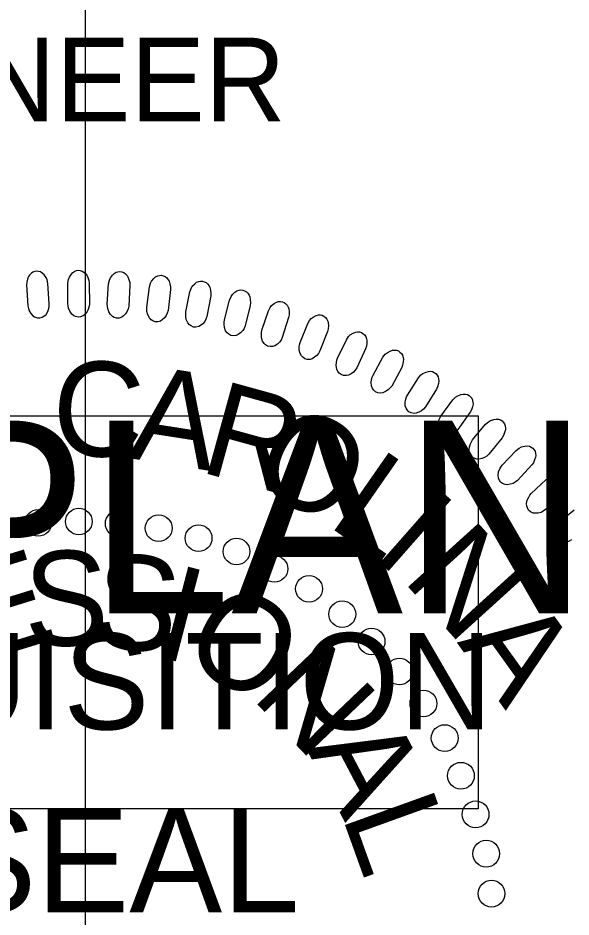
# Model space of a CAD drawing. Extents: x 505602 to 507286, y 483109 to 484209.
# Drawn here: x 507215 to 507248.1, y 484096 to 484149.8 of the extents above; entities that cross this region are included whole.
import ezdxf

# ---------------------------------------------------------------- set-up
doc = ezdxf.new("R2010")
doc.units = 0
for name, color, linetype in [('Sheet Layout Profile Border Port 2', 7, 'Continuous'), ('Sheet PE Seal Cell', 7, 'Continuous'), ('Sheet Profile CELL', 7, 'Continuous'), ('Sheet Sticker Incomplete CELL', 7, 'Continuous')]:
    doc.layers.add(name, color=color, linetype=linetype)

msp = doc.modelspace()

# ---------------------------------------------------------------- linework, layer by layer
at = {"layer": 'Sheet Layout Profile Border Port 2'}
msp.add_lwpolyline([(506919.08, 484183.712), (507219.08, 484183.712), (507219.08, 483683.712), (506919.08, 483683.712)], close=True, dxfattribs=at)
at = {"layer": 'Sheet PE Seal Cell'}
for points in [[(507218.035, 484132.707), (507218.035, 484133.933), (507218.073, 484134.153), (507218.126, 484134.293), (507218.238, 484134.462), (507218.335, 484134.572), (507218.447, 484134.651), (507218.551, 484134.691), (507218.664, 484134.711), (507218.776, 484134.691), (507218.896, 484134.661), (507219, 484134.601), (507219.105, 484134.502), (507219.165, 484134.421), (507219.232, 484134.272), (507219.292, 484134.092), (507219.314, 484133.933), (507219.321, 484132.677), (507219.299, 484132.507), (507219.253, 484132.367), (507219.164, 484132.208), (507219.052, 484132.068), (507218.954, 484131.988), (507218.797, 484131.929), (507218.648, 484131.909), (507218.499, 484131.948), (507218.394, 484131.998), (507218.266, 484132.098), (507218.147, 484132.268), (507218.08, 484132.447), (507218.05, 484132.577)], [(507216.92, 484132.698), (507216.843, 484133.922), (507216.792, 484134.139), (507216.731, 484134.274), (507216.609, 484134.437), (507216.505, 484134.54), (507216.388, 484134.613), (507216.281, 484134.646), (507216.168, 484134.659), (507216.057, 484134.632), (507215.94, 484134.595), (507215.839, 484134.529), (507215.741, 484134.422), (507215.687, 484134.339), (507215.628, 484134.186), (507215.58, 484134.003), (507215.568, 484133.842), (507215.639, 484132.587), (507215.671, 484132.42), (507215.725, 484132.283), (507215.824, 484132.129), (507215.945, 484131.997), (507216.047, 484131.924), (507216.208, 484131.873), (507216.358, 484131.863), (507216.505, 484131.912), (507216.606, 484131.969), (507216.727, 484132.076), (507216.835, 484132.253), (507216.891, 484132.436), (507216.913, 484132.568)], [(507220.394, 484132.68), (507220.472, 484133.905), (507220.522, 484134.121), (507220.584, 484134.257), (507220.707, 484134.419), (507220.81, 484134.523), (507220.927, 484134.595), (507221.034, 484134.628), (507221.148, 484134.641), (507221.258, 484134.614), (507221.376, 484134.577), (507221.476, 484134.51), (507221.575, 484134.404), (507221.629, 484134.321), (507221.687, 484134.167), (507221.735, 484133.984), (507221.748, 484133.824), (507221.675, 484132.569), (507221.643, 484132.401), (507221.589, 484132.265), (507221.489, 484132.112), (507221.369, 484131.979), (507221.267, 484131.905), (507221.106, 484131.856), (507220.955, 484131.845), (507220.809, 484131.894), (507220.708, 484131.951), (507220.587, 484132.059), (507220.479, 484132.235), (507220.423, 484132.418), (507220.401, 484132.55)], [(507222.757, 484132.505), (507222.911, 484133.722), (507222.975, 484133.935), (507223.045, 484134.067), (507223.177, 484134.221), (507223.288, 484134.318), (507223.409, 484134.382), (507223.518, 484134.409), (507223.631, 484134.415), (507223.74, 484134.381), (507223.855, 484134.336), (507223.951, 484134.264), (507224.043, 484134.151), (507224.092, 484134.065), (507224.141, 484133.908), (507224.176, 484133.722), (507224.179, 484133.561), (507224.028, 484132.314), (507223.985, 484132.148), (507223.923, 484132.016), (507223.814, 484131.868), (507223.685, 484131.744), (507223.579, 484131.677), (507223.415, 484131.637), (507223.265, 484131.636), (507223.121, 484131.695), (507223.024, 484131.757), (507222.91, 484131.872), (507222.812, 484132.056), (507222.769, 484132.242), (507222.755, 484132.375)], [(507225.096, 484132.219), (507225.326, 484133.423), (507225.404, 484133.632), (507225.482, 484133.759), (507225.624, 484133.904), (507225.74, 484133.994), (507225.865, 484134.051), (507225.975, 484134.071), (507226.089, 484134.07), (507226.195, 484134.029), (507226.307, 484133.977), (507226.399, 484133.898), (507226.483, 484133.781), (507226.527, 484133.692), (507226.565, 484133.532), (507226.59, 484133.344), (507226.582, 484133.183), (507226.354, 484131.947), (507226.299, 484131.786), (507226.229, 484131.657), (507226.111, 484131.517), (507225.975, 484131.401), (507225.864, 484131.341), (507225.699, 484131.311), (507225.548, 484131.32), (507225.409, 484131.387), (507225.316, 484131.456), (507225.21, 484131.577), (507225.124, 484131.766), (507225.091, 484131.955), (507225.087, 484132.088)], [(507227.402, 484131.745), (507227.707, 484132.933), (507227.797, 484133.136), (507227.883, 484133.258), (507228.034, 484133.395), (507228.155, 484133.477), (507228.284, 484133.526), (507228.395, 484133.538), (507228.509, 484133.53), (507228.612, 484133.483), (507228.721, 484133.424), (507228.807, 484133.34), (507228.883, 484133.218), (507228.922, 484133.125), (507228.949, 484132.963), (507228.963, 484132.775), (507228.945, 484132.614), (507228.639, 484131.395), (507228.575, 484131.237), (507228.496, 484131.113), (507228.37, 484130.981), (507228.227, 484130.874), (507228.113, 484130.82), (507227.946, 484130.802), (507227.796, 484130.82), (507227.662, 484130.896), (507227.573, 484130.97), (507227.474, 484131.098), (507227.4, 484131.292), (507227.38, 484131.483), (507227.383, 484131.615)], [(507229.651, 484131.123), (507230.031, 484132.289), (507230.134, 484132.487), (507230.227, 484132.603), (507230.386, 484132.73), (507230.513, 484132.804), (507230.644, 484132.845), (507230.756, 484132.85), (507230.869, 484132.835), (507230.969, 484132.781), (507231.073, 484132.715), (507231.155, 484132.626), (507231.223, 484132.499), (507231.255, 484132.405), (507231.273, 484132.242), (507231.274, 484132.053), (507231.247, 484131.894), (507230.865, 484130.697), (507230.791, 484130.542), (507230.705, 484130.423), (507230.571, 484130.299), (507230.42, 484130.201), (507230.304, 484130.155), (507230.136, 484130.147), (507229.987, 484130.175), (507229.858, 484130.259), (507229.774, 484130.338), (507229.684, 484130.472), (507229.622, 484130.67), (507229.614, 484130.862), (507229.626, 484130.995)], [(507231.935, 484130.388), (507232.387, 484131.528), (507232.502, 484131.718), (507232.602, 484131.829), (507232.769, 484131.945), (507232.9, 484132.012), (507233.034, 484132.044), (507233.145, 484132.043), (507233.257, 484132.02), (507233.353, 484131.96), (507233.454, 484131.888), (507233.529, 484131.794), (507233.59, 484131.663), (507233.616, 484131.567), (507233.624, 484131.403), (507233.613, 484131.214), (507233.575, 484131.057), (507233.119, 484129.886), (507233.035, 484129.737), (507232.942, 484129.624), (507232.8, 484129.509), (507232.645, 484129.42), (507232.525, 484129.381), (507232.357, 484129.384), (507232.211, 484129.421), (507232.086, 484129.513), (507232.007, 484129.597), (507231.926, 484129.737), (507231.878, 484129.939), (507231.881, 484130.13), (507231.901, 484130.262)], [(507234.176, 484129.454), (507234.699, 484130.563), (507234.826, 484130.746), (507234.933, 484130.85), (507235.107, 484130.956), (507235.241, 484131.014), (507235.376, 484131.038), (507235.488, 484131.029), (507235.598, 484131), (507235.691, 484130.934), (507235.787, 484130.856), (507235.856, 484130.757), (507235.908, 484130.622), (507235.928, 484130.525), (507235.925, 484130.36), (507235.903, 484130.173), (507235.855, 484130.019), (507235.326, 484128.879), (507235.234, 484128.735), (507235.134, 484128.628), (507234.984, 484128.521), (507234.824, 484128.443), (507234.701, 484128.412), (507234.534, 484128.425), (507234.39, 484128.471), (507234.273, 484128.57), (507234.199, 484128.66), (507234.126, 484128.805), (507234.091, 484129.009), (507234.106, 484129.2), (507234.134, 484129.33)], [(507236.3, 484128.439), (507236.891, 484129.513), (507237.03, 484129.687), (507237.143, 484129.785), (507237.323, 484129.879), (507237.461, 484129.928), (507237.598, 484129.944), (507237.709, 484129.929), (507237.816, 484129.892), (507237.905, 484129.82), (507237.995, 484129.736), (507238.058, 484129.634), (507238.102, 484129.496), (507238.116, 484129.397), (507238.103, 484129.234), (507238.068, 484129.048), (507238.012, 484128.897), (507237.412, 484127.792), (507237.311, 484127.655), (507237.204, 484127.554), (507237.049, 484127.457), (507236.883, 484127.389), (507236.759, 484127.366), (507236.593, 484127.389), (507236.452, 484127.444), (507236.34, 484127.551), (507236.273, 484127.645), (507236.21, 484127.794), (507236.187, 484128), (507236.214, 484128.19), (507236.25, 484128.318)], [(507238.358, 484127.254), (507239.016, 484128.289), (507239.165, 484128.454), (507239.284, 484128.544), (507239.469, 484128.627), (507239.61, 484128.668), (507239.748, 484128.675), (507239.857, 484128.652), (507239.963, 484128.609), (507240.047, 484128.532), (507240.131, 484128.442), (507240.188, 484128.336), (507240.223, 484128.196), (507240.23, 484128.096), (507240.207, 484127.934), (507240.161, 484127.75), (507240.095, 484127.604), (507239.427, 484126.539), (507239.317, 484126.408), (507239.205, 484126.314), (507239.044, 484126.228), (507238.874, 484126.17), (507238.749, 484126.154), (507238.584, 484126.188), (507238.448, 484126.252), (507238.343, 484126.365), (507238.281, 484126.464), (507238.227, 484126.616), (507238.218, 484126.823), (507238.257, 484127.01), (507238.301, 484127.136)], [(507240.358, 484125.98), (507241.079, 484126.972), (507241.238, 484127.128), (507241.363, 484127.211), (507241.553, 484127.282), (507241.696, 484127.313), (507241.834, 484127.312), (507241.942, 484127.282), (507242.045, 484127.233), (507242.124, 484127.151), (507242.202, 484127.056), (507242.252, 484126.946), (507242.278, 484126.804), (507242.28, 484126.704), (507242.246, 484126.543), (507242.189, 484126.363), (507242.113, 484126.221), (507241.38, 484125.2), (507241.262, 484125.077), (507241.144, 484124.99), (507240.978, 484124.913), (507240.805, 484124.866), (507240.679, 484124.859), (507240.517, 484124.903), (507240.385, 484124.975), (507240.287, 484125.095), (507240.232, 484125.197), (507240.187, 484125.352), (507240.191, 484125.56), (507240.242, 484125.744), (507240.294, 484125.867)], [(507242.252, 484124.564), (507243.035, 484125.509), (507243.203, 484125.654), (507243.332, 484125.728), (507243.527, 484125.788), (507243.672, 484125.81), (507243.809, 484125.8), (507243.915, 484125.764), (507244.014, 484125.707), (507244.088, 484125.622), (507244.161, 484125.522), (507244.203, 484125.409), (507244.22, 484125.265), (507244.216, 484125.166), (507244.172, 484125.008), (507244.104, 484124.831), (507244.02, 484124.694), (507243.224, 484123.721), (507243.098, 484123.605), (507242.974, 484123.526), (507242.804, 484123.46), (507242.628, 484123.424), (507242.502, 484123.424), (507242.343, 484123.478), (507242.216, 484123.559), (507242.126, 484123.685), (507242.077, 484123.79), (507242.043, 484123.948), (507242.059, 484124.154), (507242.122, 484124.336), (507242.182, 484124.455)], [(507244.024, 484123.05), (507244.864, 484123.944), (507245.041, 484124.079), (507245.175, 484124.145), (507245.373, 484124.191), (507245.519, 484124.205), (507245.655, 484124.186), (507245.759, 484124.144), (507245.855, 484124.081), (507245.922, 484123.99), (507245.989, 484123.886), (507246.025, 484123.771), (507246.032, 484123.626), (507246.022, 484123.527), (507245.968, 484123.372), (507245.889, 484123.201), (507245.796, 484123.069), (507244.94, 484122.148), (507244.808, 484122.04), (507244.68, 484121.969), (507244.505, 484121.914), (507244.328, 484121.889), (507244.202, 484121.897), (507244.047, 484121.961), (507243.924, 484122.049), (507243.843, 484122.181), (507243.801, 484122.288), (507243.776, 484122.448), (507243.805, 484122.654), (507243.879, 484122.83), (507243.946, 484122.945)], [(507245.768, 484121.357), (507246.663, 484122.196), (507246.848, 484122.319), (507246.986, 484122.376), (507247.186, 484122.411), (507247.333, 484122.415), (507247.467, 484122.388), (507247.569, 484122.339), (507247.66, 484122.271), (507247.722, 484122.175), (507247.782, 484122.067), (507247.81, 484121.95), (507247.809, 484121.806), (507247.791, 484121.707), (507247.728, 484121.556), (507247.639, 484121.39), (507247.538, 484121.264), (507246.626, 484120.399), (507246.487, 484120.299), (507246.355, 484120.236), (507246.178, 484120.193), (507245.999, 484120.179), (507245.874, 484120.195), (507245.723, 484120.268), (507245.606, 484120.364), (507245.533, 484120.5), (507245.498, 484120.61), (507245.483, 484120.771), (507245.525, 484120.974), (507245.61, 484121.147), (507245.684, 484121.257)]]:
    msp.add_lwpolyline(points, close=True, dxfattribs=at)
msp.add_lwpolyline([(507248.177, 484118.6), (507248.032, 484118.51), (507247.895, 484118.455), (507247.715, 484118.423), (507247.536, 484118.42), (507247.413, 484118.444), (507247.266, 484118.527), (507247.156, 484118.63), (507247.092, 484118.77), (507247.063, 484118.882), (507247.059, 484119.044), (507247.114, 484119.244), (507247.209, 484119.411), (507247.29, 484119.516), (507247.38, 484119.61), (507248.326, 484120.392)], dxfattribs=at)
for centre in [(507216.263, 484119.611), (507218.692, 484119.69), (507221.081, 484119.569), (507223.47, 484119.29), (507225.858, 484118.692), (507228.127, 484117.894), (507230.396, 484116.858), (507232.466, 484115.662), (507234.456, 484114.147), (507236.208, 484112.513), (507237.879, 484110.72), (507239.312, 484108.808), (507240.585, 484106.736), (507241.557, 484104.486), (507242.432, 484102.175), (507243.069, 484099.825), (507243.386, 484097.435)]:
    msp.add_circle(centre, 0.801, dxfattribs=at)
at = {"layer": 'Sheet Sticker Incomplete CELL'}
msp.add_lwpolyline([(507095.597, 484102.505), (507095.597, 484126.005), (507242.597, 484126.005), (507242.597, 484102.505)], close=True, dxfattribs=at)

# ---------------------------------------------------------------- texts
at = {"layer": 'Sheet PE Seal Cell'}
for s, height, rotation, p in [('C', 5.669, 357.5877, (507217.01, 484123.701)), ('A', 5.669, 351.0983, (507221.585, 484123.493)), ('R', 5.669, 344.609, (507225.792, 484122.699)), ('O', 5.669, 331.6302, (507228.747, 484122.045)), ('L', 5.669, 325.1409, (507233.48, 484119.513)), ('I', 5.669, 318.6515, (507236.173, 484117.66)), ('N', 5.669, 312.1622, (507237.978, 484116.24)), ('S', 5.669, 1.289, (507215.468, 484112.208)), ('E', 5.669, 17.1686, (507212.701, 484111.249)), ('S', 5.669, 353.3492, (507219.329, 484112.31)), ('I', 5.669, 345.4094, (507223.13, 484111.678)), ('O', 5.669, 329.5298, (507224.633, 484111.506)), ('A', 5.669, 305.6728, (507241.298, 484112.46)), ('N', 5.669, 313.6502, (507228.945, 484109.202)), ('A', 5.669, 297.7707, (507232.282, 484106.121)), ('L', 5.669, 289.8309, (507234.406, 484102.126)), ('SEAL', 6.2363, 359.9814, (507210.585, 484096.314))]:
    msp.add_text(s, height=height, rotation=rotation, dxfattribs=at).set_placement(p)
at = {"layer": 'Sheet Profile CELL'}
msp.add_text('ENGINEER', height=5.0001, dxfattribs=at).set_placement((507196.142, 484143.624))
at = {"layer": 'Sheet Sticker Incomplete CELL'}
for s, height, p in [('INCOMPLETE PLANS', 11.52, (507104.547, 484114.205)), ('DO NOT USE FOR R/W ACQUISITION', 5.76, (507107.797, 484107.255))]:
    msp.add_text(s, height=height, dxfattribs=at).set_placement(p)

doc.saveas('drawing.dxf')
